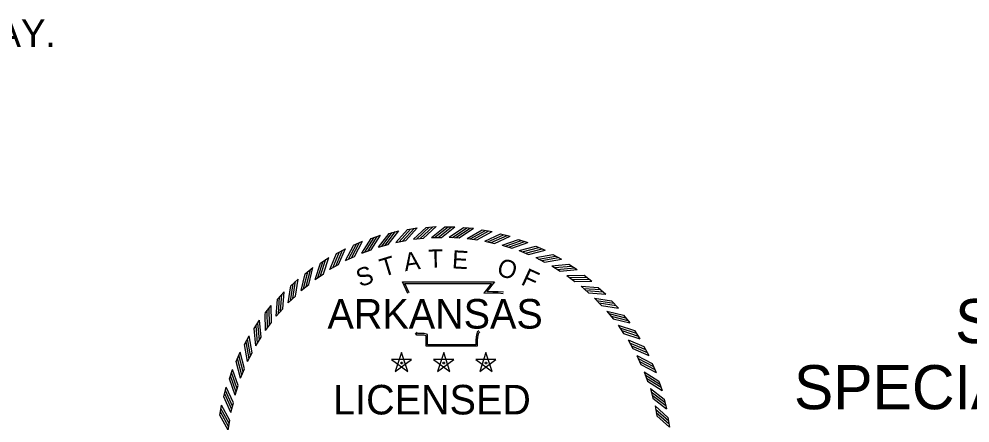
# Model space of a CAD drawing. Extents: x 16 to 1228740, y 11 to 152440.
# Drawn here: x 17.6145 to 17.9747, y 10.9152 to 11.0683 of the extents above; entities that cross this region are included whole.
import ezdxf

# ---------------------------------------------------------------- set-up
doc = ezdxf.new("R2010")
doc.units = 0
for name, color, linetype in [('B_Copy In', 7, 'Continuous'), ('B_Text', 7, 'Continuous'), ('STAMP_FRED', 7, 'Continuous')]:
    doc.layers.add(name, color=color, linetype=linetype)

msp = doc.modelspace()

# ---------------------------------------------------------------- linework, layer by layer
at = {"layer": 'STAMP_FRED'}
for p, q in [((17.75468, 10.98707), (17.75833, 10.98803)), ((17.76165, 10.98849), (17.76536, 10.98915)), ((17.7687, 10.98933), (17.77246, 10.98968)), ((17.77584, 10.98954), (17.77961, 10.98954)), ((17.7829, 10.98926), (17.78666, 10.98899)), ((17.78995, 10.98835), (17.79367, 10.98776)), ((17.74123, 10.98253), (17.74467, 10.98407)), ((17.74786, 10.98508), (17.75142, 10.98633)), ((17.75728, 10.98365), (17.761, 10.9843)), ((17.76395, 10.98487), (17.76771, 10.98521)), ((17.7707, 10.98553), (17.77447, 10.98553)), ((17.77748, 10.98564), (17.78125, 10.98536)), ((17.78424, 10.98518), (17.78798, 10.9846)), ((17.79095, 10.98417), (17.79462, 10.98328)), ((17.7969, 10.98685), (17.80056, 10.98596)), ((17.8037, 10.98479), (17.80727, 10.9836)), ((17.73483, 10.97944), (17.73813, 10.98126)), ((17.74435, 10.97958), (17.74791, 10.98084)), ((17.75073, 10.98188), (17.75438, 10.98284)), ((17.79755, 10.98261), (17.80113, 10.98142)), ((17.804, 10.98051), (17.80747, 10.97902)), ((17.8103, 10.98217), (17.81377, 10.98069)), ((17.72871, 10.97583), (17.73184, 10.97792)), ((17.73818, 10.97676), (17.74163, 10.97831)), ((17.81025, 10.97788), (17.81359, 10.97611)), ((17.81667, 10.97902), (17.82, 10.97726)), ((17.7229, 10.97173), (17.72586, 10.97407)), ((17.73227, 10.97344), (17.73558, 10.97527)), ((17.81626, 10.97475), (17.81944, 10.97271)), ((17.82276, 10.97535), (17.82593, 10.97332)), ((17.71746, 10.96717), (17.72021, 10.96975)), ((17.72665, 10.96964), (17.72979, 10.97174)), ((17.822, 10.97113), (17.825, 10.96883)), ((17.82852, 10.97119), (17.83152, 10.9689)), ((17.72136, 10.96539), (17.72432, 10.96774)), ((17.82741, 10.96705), (17.83022, 10.96451)), ((17.83392, 10.96657), (17.83672, 10.96404)), ((17.71241, 10.96217), (17.71493, 10.96496)), ((17.71645, 10.96072), (17.7192, 10.96331)), ((17.83247, 10.96253), (17.83506, 10.95977)), ((17.70779, 10.95677), (17.71007, 10.95976)), ((17.83892, 10.96152), (17.8415, 10.95877)), ((17.71193, 10.95566), (17.71447, 10.95846)), ((17.83714, 10.95761), (17.83949, 10.95465)), ((17.84348, 10.95608), (17.84583, 10.95312)), ((17.70363, 10.95101), (17.70566, 10.95418)), ((17.70785, 10.95025), (17.71014, 10.95325)), ((17.84139, 10.95233), (17.84349, 10.94918)), ((17.69996, 10.94492), (17.70172, 10.94825)), ((17.84758, 10.95027), (17.84967, 10.94713)), ((17.70423, 10.94451), (17.70627, 10.94769)), ((17.84519, 10.94671), (17.84702, 10.9434)), ((17.6968, 10.93855), (17.69829, 10.94202)), ((17.7011, 10.9385), (17.70286, 10.94184)), ((17.75937, 10.94198), (17.75701, 10.93474)), ((17.76172, 10.93475), (17.75937, 10.94199)), ((17.77536, 10.94198), (17.773, 10.93474)), ((17.77771, 10.93475), (17.77536, 10.94199)), ((17.79135, 10.94198), (17.78899, 10.93474)), ((17.7937, 10.93475), (17.79135, 10.94199)), ((17.84851, 10.9408), (17.85006, 10.93735)), ((17.85119, 10.94415), (17.85301, 10.94085)), ((17.76317, 10.93922), (17.75556, 10.93922)), ((17.75557, 10.93922), (17.76172, 10.93474)), ((17.75702, 10.93475), (17.76318, 10.93922)), ((17.75883, 10.938), (17.75996, 10.938)), ((17.75937, 10.93841), (17.75937, 10.93745)), ((17.77916, 10.93922), (17.77155, 10.93922)), ((17.77156, 10.93922), (17.77771, 10.93474)), ((17.77301, 10.93475), (17.77917, 10.93922)), ((17.77482, 10.938), (17.77595, 10.938)), ((17.77536, 10.93841), (17.77536, 10.93745)), ((17.79515, 10.93922), (17.78754, 10.93922)), ((17.78755, 10.93922), (17.7937, 10.93474)), ((17.789, 10.93475), (17.79516, 10.93922)), ((17.79081, 10.938), (17.79194, 10.938)), ((17.79136, 10.93841), (17.79136, 10.93745)), ((17.85428, 10.93775), (17.85582, 10.93431)), ((17.69419, 10.93195), (17.69538, 10.93552)), ((17.69847, 10.93224), (17.69996, 10.93572)), ((17.85133, 10.93463), (17.85259, 10.93107)), ((17.85683, 10.93112), (17.85808, 10.92756)), ((17.69212, 10.92514), (17.69302, 10.92881)), ((17.69637, 10.9258), (17.69756, 10.92938)), ((17.85363, 10.92825), (17.85459, 10.92459)), ((17.69481, 10.9192), (17.6957, 10.92287)), ((17.85882, 10.92429), (17.85978, 10.92065)), ((17.69063, 10.9182), (17.69122, 10.92192)), ((17.8554, 10.9217), (17.85606, 10.91798)), ((17.69379, 10.91249), (17.69438, 10.91622)), ((17.86024, 10.91733), (17.8609, 10.91362))]:
    msp.add_line(p, q, dxfattribs=at)
for points in [[(17.75316, 10.98253), (17.75711, 10.98772)], [(17.75438, 10.98284), (17.75833, 10.98803)], [(17.75727, 10.98364), (17.76164, 10.98849)], [(17.75847, 10.98384), (17.76284, 10.98869)], [(17.75975, 10.9841), (17.76412, 10.98894)], [(17.76099, 10.98431), (17.76536, 10.98915)], [(17.76394, 10.98486), (17.7687, 10.98933)], [(17.76515, 10.98496), (17.76991, 10.98943)], [(17.76645, 10.98511), (17.77121, 10.98958)], [(17.76771, 10.98522), (17.77246, 10.98968)], [(17.77069, 10.98553), (17.77584, 10.98954)], [(17.77191, 10.98552), (17.77705, 10.98953)], [(17.77321, 10.98555), (17.77836, 10.98956)], [(17.77447, 10.98554), (17.77961, 10.98955)], [(17.77747, 10.98564), (17.7829, 10.98926)], [(17.77868, 10.98554), (17.78411, 10.98916)], [(17.77999, 10.98547), (17.78541, 10.98909)], [(17.78124, 10.98536), (17.78667, 10.98899)], [(17.78424, 10.98518), (17.78994, 10.98834)], [(17.78544, 10.98498), (17.79114, 10.98814)], [(17.78673, 10.98481), (17.79244, 10.98797)], [(17.78797, 10.9846), (17.79368, 10.98776)], [(17.74162, 10.97831), (17.74467, 10.98408)], [(17.74435, 10.97957), (17.74786, 10.98507)], [(17.74549, 10.97997), (17.74901, 10.98546)], [(17.74672, 10.98043), (17.75023, 10.98593)], [(17.74791, 10.98084), (17.75142, 10.98634)], [(17.75073, 10.98188), (17.75468, 10.98706)], [(17.7519, 10.98217), (17.75586, 10.98736)], [(17.79094, 10.98417), (17.79689, 10.98685)], [(17.79212, 10.98387), (17.79807, 10.98655)], [(17.7934, 10.98359), (17.79935, 10.98627)], [(17.79462, 10.98328), (17.80056, 10.98596)], [(17.79754, 10.98261), (17.80369, 10.98479)], [(17.79869, 10.98221), (17.80484, 10.9844)], [(17.79994, 10.98183), (17.80609, 10.98401)], [(17.73447, 10.97467), (17.73703, 10.98067)], [(17.73557, 10.97527), (17.73813, 10.98127)], [(17.73818, 10.97675), (17.74123, 10.98252)], [(17.73929, 10.97724), (17.74234, 10.98301)], [(17.74047, 10.9778), (17.74352, 10.98357)], [(17.80113, 10.98142), (17.80728, 10.9836)], [(17.80399, 10.98051), (17.8103, 10.98217)], [(17.8051, 10.98002), (17.81141, 10.98169)], [(17.80632, 10.97953), (17.81262, 10.9812)], [(17.80747, 10.97903), (17.81377, 10.98069)], [(17.72874, 10.97105), (17.73079, 10.97724)], [(17.72979, 10.97174), (17.73184, 10.97793)], [(17.73227, 10.97343), (17.73483, 10.97943)], [(17.73333, 10.97401), (17.73589, 10.98001)], [(17.81024, 10.97788), (17.81667, 10.97902)], [(17.81131, 10.9773), (17.81773, 10.97844)], [(17.81248, 10.97672), (17.8189, 10.97786)], [(17.81359, 10.97612), (17.82001, 10.97726)], [(17.72333, 10.96697), (17.72487, 10.97331)], [(17.72432, 10.96774), (17.72586, 10.97408)], [(17.72665, 10.96963), (17.7287, 10.97583)], [(17.72766, 10.9703), (17.72972, 10.97649)], [(17.81626, 10.97475), (17.82275, 10.97535)], [(17.81727, 10.97408), (17.82377, 10.97469)], [(17.81839, 10.9734), (17.82489, 10.97401)], [(17.81944, 10.97271), (17.82594, 10.97332)], [(17.7192, 10.96331), (17.72021, 10.96975)], [(17.72136, 10.96539), (17.7229, 10.97173)], [(17.72232, 10.96613), (17.72386, 10.97247)], [(17.82199, 10.97113), (17.82851, 10.97119)], [(17.82295, 10.97038), (17.82947, 10.97045)], [(17.82401, 10.96961), (17.83053, 10.96968)], [(17.71645, 10.96072), (17.71745, 10.96716)], [(17.71734, 10.96154), (17.71835, 10.96798)], [(17.71827, 10.96245), (17.71928, 10.9689)], [(17.7618, 10.96431), (17.75979, 10.96867), (17.79455, 10.96869), (17.79165, 10.96504), (17.79401, 10.96507), (17.79598, 10.96509), (17.79796, 10.96488)], [(17.7623, 10.96454), (17.76065, 10.96811), (17.79341, 10.96813), (17.7905, 10.96447), (17.79402, 10.96452), (17.79596, 10.96454), (17.7979, 10.96433)], [(17.825, 10.96884), (17.83152, 10.9689)], [(17.82741, 10.96705), (17.83391, 10.96657)], [(17.8283, 10.96622), (17.83481, 10.96575)], [(17.71275, 10.95655), (17.71323, 10.96305)], [(17.71361, 10.95754), (17.71408, 10.96404)], [(17.71446, 10.95846), (17.71493, 10.96497)], [(17.82929, 10.96537), (17.8358, 10.9649)], [(17.83021, 10.96452), (17.83672, 10.96404)], [(17.83247, 10.96253), (17.83891, 10.96152)], [(17.70937, 10.95226), (17.7093, 10.95878)], [(17.71014, 10.95325), (17.71007, 10.95977)], [(17.71193, 10.95566), (17.7124, 10.96216)], [(17.83329, 10.96164), (17.83973, 10.96063)], [(17.83421, 10.9607), (17.84065, 10.9597)], [(17.83506, 10.95978), (17.8415, 10.95877)], [(17.70785, 10.95024), (17.70778, 10.95676)], [(17.7086, 10.9512), (17.70853, 10.95772)], [(17.83714, 10.95761), (17.84348, 10.95608)], [(17.83788, 10.95666), (17.84422, 10.95512)], [(17.83872, 10.95565), (17.84506, 10.95411)], [(17.7049, 10.94552), (17.70429, 10.95202)], [(17.70558, 10.94664), (17.70497, 10.95313)], [(17.70626, 10.94769), (17.70566, 10.95419)], [(17.83949, 10.95466), (17.84583, 10.95312)], [(17.84139, 10.95233), (17.84758, 10.95027)], [(17.70286, 10.94183), (17.70172, 10.94826)], [(17.70423, 10.9445), (17.70363, 10.951)], [(17.78908, 10.94974), (17.78848, 10.94926), (17.78829, 10.94854), (17.78809, 10.94674), (17.78809, 10.94433), (17.76868, 10.94433), (17.76868, 10.94758), (17.76868, 10.9483), (17.76789, 10.94854), (17.76513, 10.94854), (17.76464, 10.94929)], [(17.78873, 10.95017), (17.788, 10.94958), (17.78774, 10.94864), (17.78754, 10.94677), (17.78754, 10.94488), (17.76923, 10.94488), (17.76923, 10.94758), (17.76923, 10.94871), (17.76798, 10.94909), (17.76543, 10.94909), (17.7651, 10.94959)], [(17.84205, 10.95131), (17.84824, 10.94926)], [(17.8428, 10.95024), (17.84899, 10.94818)], [(17.84349, 10.94919), (17.84968, 10.94713)], [(17.7011, 10.93849), (17.69996, 10.94491)], [(17.70168, 10.93956), (17.70054, 10.94598)], [(17.70226, 10.94073), (17.70112, 10.94715)], [(17.84518, 10.94671), (17.85118, 10.94415)], [(17.84576, 10.94564), (17.85176, 10.94308)], [(17.84642, 10.94451), (17.85242, 10.94195)], [(17.69945, 10.93457), (17.69778, 10.94087)], [(17.69995, 10.93572), (17.69829, 10.94202)], [(17.84702, 10.94341), (17.85302, 10.94085)], [(17.8485, 10.9408), (17.85427, 10.93775)], [(17.69847, 10.93224), (17.69681, 10.93855)], [(17.69896, 10.93335), (17.69729, 10.93966)], [(17.84899, 10.93969), (17.85476, 10.93664)], [(17.84956, 10.9385), (17.85532, 10.93546)], [(17.85006, 10.93735), (17.85583, 10.93431)], [(17.69715, 10.92819), (17.69497, 10.93434)], [(17.69756, 10.92938), (17.69538, 10.93553)], [(17.85133, 10.93463), (17.85682, 10.93112)], [(17.85172, 10.93348), (17.85722, 10.92997)], [(17.69637, 10.92579), (17.69419, 10.93194)], [(17.69676, 10.92694), (17.69458, 10.93309)], [(17.85218, 10.93226), (17.85768, 10.92875)], [(17.85259, 10.93107), (17.85809, 10.92756)], [(17.69511, 10.92037), (17.69242, 10.92632)], [(17.69539, 10.92165), (17.69271, 10.92759)], [(17.6957, 10.92287), (17.69301, 10.92881)], [(17.85363, 10.92825), (17.85882, 10.9243)], [(17.85393, 10.92708), (17.85911, 10.92312)], [(17.69481, 10.91919), (17.69213, 10.92514)], [(17.85429, 10.92582), (17.85947, 10.92186)], [(17.85459, 10.9246), (17.85978, 10.92065)], [(17.694, 10.91368), (17.69083, 10.91939)], [(17.69417, 10.91498), (17.69101, 10.92069)], [(17.69438, 10.91622), (17.69122, 10.92193)], [(17.85539, 10.92171), (17.86024, 10.91734)], [(17.85559, 10.92051), (17.86044, 10.91614)], [(17.85585, 10.91922), (17.86069, 10.91486)], [(17.6938, 10.91249), (17.69063, 10.91819)], [(17.85606, 10.91799), (17.8609, 10.91362)]]:
    msp.add_lwpolyline(points, dxfattribs=at)

# ---------------------------------------------------------------- texts
at = {"layer": 'B_Copy In'}
for s, p in [('SCHEDULE OF BRIDGE QUANTITIES', (17.96903, 10.94549)), ('SPECIALIZED BRIDGE DECK REHAB. (2021) (S)', (17.908, 10.92044))]:
    msp.add_text(s, height=0.0167, dxfattribs=at).set_placement(p)
at = {"layer": 'B_Text'}
msp.add_text('MODIFICATION OF EXISTING BRIDGE STRUCTURE INCLUDES MODIFICATION OF BACKWALLS TO MATCH GRADE INCREASE OF LMC OVERLAY.', height=0.01041667, dxfattribs=at).set_placement((16.66099, 11.0577))
at = {"layer": 'STAMP_FRED'}
for s, rotation, p in [('T', 1.4789, (17.76959, 10.97405)), ('E', 356.672, (17.77837, 10.97384)), ('T', 16.9015, (17.75241, 10.97051)), ('A', 8.6788, (17.76074, 10.97268)), ('O', 341.2218, (17.79502, 10.97149)), ('S', 19.7726, (17.74369, 10.96659)), ('F', 335.3628, (17.80426, 10.96787))]:
    msp.add_text(s, height=0.00686, rotation=rotation, dxfattribs=at).set_placement(p)
for s, p in [('ARKANSAS', (17.73136, 10.95099)), ('LICENSED', (17.7335, 10.91846))]:
    msp.add_text(s, height=0.011193, dxfattribs=at).set_placement(p)

doc.saveas('drawing.dxf')
